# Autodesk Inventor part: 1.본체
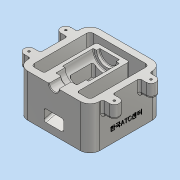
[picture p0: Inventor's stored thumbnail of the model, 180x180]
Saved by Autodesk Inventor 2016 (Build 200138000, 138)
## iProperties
Created: 2018-01
Part Number: 1.본체
Material: 알루미늄 6061
Document SubType Name: Modeling
Designer: Administrator
Density: 2.7 g/cm^3
Appearance: 알루미늄 - 평지
Mass: 995.363 g
Surface Area: 835.116 cm^2
Volume: 368.653 cm^3
Author: Administrator
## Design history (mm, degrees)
sketch "스케치1"
  geometry: L1 (-55, -55)-(55, -55); L2 (55, -55)-(55, 55); L3 (55, 55)-(-55, 55); L4 (-55, 55)-(-55, -55); L5 (-55, -55)-(55, 55); L6 (55, -55)-(-55, 55); 1 further point
  constraints: 12 end point, 2 midpoint, 2 parallel, 1 horizontal, 1 perpendicular
  dimensions: "d0" = 110 distance of L3.end L2.end; "d1" = 110 distance of L2.end L1.end
extrude "돌출1" new body sketch "스케치1" distance "d2" = 65; taper "d3" = 0 deg
sketch "스케치2"
  geometry: L1 (-55, -55)-(55, -55) reference; L2 (55, -55)-(55, 55) reference; L3 (55, 55)-(-55, 55) reference; L4 (-55, 55)-(-55, -55) reference; L5 (55, 35.5)-(65, 35.5); L6 (65, 35.5)-(65, 20.5); L7 (65, 20.5)-(55, 20.5); L8 (55, 20.5)-(55, 35.5); A1 r 7.5 centre (65, 28) between (65, 20.5) and (65, 35.5); 1 further point
  constraints: 8 end point, 2 parallel, 2 point on circle, 1 centre point, 1 horizontal, 1 midpoint, 1 perpendicular, 1 point on line
  dimensions: "d5" = 7.5 radius of A1; "d6" = 10 distance of L6.end L7.end; "d70" = 27 distance from line of A1.centre L3
extrude "돌출2" join sketch "스케치2" distance "d7" = 20; taper "d8" = 0 deg
sketch "스케치3"
  geometry: L1 (-45, 45)-(45, 45); L2 (45, 45)-(45, -45); L3 (45, -45)-(-45, -45); L4 (-45, -45)-(-45, 45); L5 (-45, 45)-(45, -45); L6 (45, 45)-(-45, -45); 1 further point
  constraints: 12 end point, 2 midpoint, 2 parallel, 1 horizontal, 1 perpendicular
  dimensions: "d9" = 90 distance of L2.end L3.end; "d10" = 90 distance of L1.end L2.end
extrude "돌출3" cut sketch "스케치3" stored distance "d11" = 20; taper "d12" = 0 deg
sketch "스케치4"
  geometry: L1 (-55, -55)-(55, -55) reference; L2 (55, 55)-(-55, 55) reference; L3 (-25, 35)-(25, 35); L4 (25, 35)-(25, -55); L5 (25, -55)-(-25, -55); L6 (-25, -55)-(-25, 35); 2 further points
  constraints: 8 end point, 2 parallel, 1 horizontal, 1 midpoint, 1 perpendicular, 1 point on line, 1 vertical alignment
  dimensions: "d13" = 50 distance between parallel lines of L4 L6; "d14" = 20 distance between parallel lines of L2 L3
extrude "돌출4" join sketch "스케치4" distance "d15" = 65; taper "d16" = 0 deg
sketch "스케치5"
  geometry: L1 (-55, 0)-(-55, 65) reference; L2 (-55, 65)-(-55, 57.5); L3 (-55, 57.5)-(-36, 57.5); L4 (-36, 57.5)-(-36, 49); L5 (-36, 49)-(-22, 49); L6 (-22, 49)-(-22, 45); L7 (-22, 45)-(25, 45); L8 (55, 65)-(35.5, 65) reference; L9 (-35.5, 65)-(-55, 65) reference; L10 (-55, 65)-(30, 65); L11 (-45, 65)-(45, 65) reference; L12 (25, 45)-(25, 50); L13 (25, 50)-(30, 50); L14 (30, 50)-(30, 65); 1 further point
  constraints: 20 end point, 6 perpendicular, 2 point on line, 1 collinear, 1 horizontal, 1 vertical
  dimensions: "d17" = 19 distance of L2.end L3.end; "d18" = 14 distance of L4.end L5.end; "d19" = 47 distance of L6.end L7.end; "d20" = 5 distance of L12.end L13.end; "d21" = 15 diameter of L3 L10; "d22" = 32 diameter of L5 L10; "d23" = 40 diameter of L7 L10; "d25" = 15 distance from line of L10.end L13
revolve "회전1" sketch "스케치5" stored, may be unused: angle "d26" = 90 deg
sketch "스케치6"
  geometry: L1 (35, 0)-(35, 30); L2 (35, 65)-(35, 0) reference; L3 (35, 30)-(-45, 8.564); L4 (-45, 8.564)-(-45, 0); L5 (45, 0)-(-45, 0) reference; L6 (-45, 0)-(35, 0); L7 (-22, 45)-(25, 45) reference; L8 (-17, 45)-(20, 45); L9 (-55, 0)-(-55, 65) reference; L10 (-55, 11.061)-(-55, 29.061); L11 (-55, 29.061)-(-17, 39.243); L12 (-17, 39.243)-(-17, 45); L13 (-45, 65)-(-45, 0) reference; L14 (-55, 11.061)-(20, 31.157); L15 (20, 31.157)-(20, 45); 3 further points
  constraints: 20 end point, 6 point on line, 4 parallel, 2 midpoint, 1 coincident, 1 collinear
  dimensions: "d27" = 30 distance of L1.start L1.end; "d28" = 105 deg angle of L4 L3; "d29" = 5 distance between parallel lines of L3 L14; "d30" = 37 distance of L8.start L8.end; "d31" = 75 deg angle of L9 L11; "d32" = 18 distance of L10.start L10.end; "d54" = 10 distance between parallel lines of L9 L4
extrude "돌출5" cut sketch "스케치6" stored distance "d33" = 30; taper "d34" = 0 deg
extrude "돌출6" cut sketch "스케치6" stored distance "d35" = 50; taper "d36" = 0 deg
node "작업 평면1"
sketch "스케치7"
  geometry: L1 (-15, -17)-(15, -17); L2 (15, -17)-(15, 20); L3 (15, 20)-(-15, 20); L4 (-15, 20)-(-15, -17); L5 (0, 20)-(0, -17) reference; L6 (-15, -17)-(15, 20); L7 (15, -17)-(-15, 20); 2 further points
  constraints: 12 end point, 3 midpoint, 2 parallel, 1 horizontal, 1 perpendicular
  dimensions: "d38" = 30 distance of L3.end L2.end; "d39" = 37 distance of L2.end L1.end
extrude "돌출7" cut sketch "스케치7" stored distance "d40" = 50; taper "d41" = 0 deg
fillet "모깎기1" dims "d42" = 1
fillet "모깎기2" dims "d43" = 3
fillet "모깎기3" dims "d44" = 15
fillet "모깎기4" dims "d45" = 3
fillet "모깎기5" dims "d46" = 3
fillet "모깎기6" dims "d48" = 5
chamfer "모따기1" distance "d50" = 1; stored, may be unused: second distance "d51" = 2, angle "d52" = 45 deg
fillet "모깎기7" dims "d53" = 3
hole "구멍1" diameter "d59" = 3.242; stored, may be unused: countersink angle "d63" = 90 deg, drill point angle "d65" = 118 deg; dims "d57" = 10, "d58" = 10, "d60" = 9, "d61" = 4, "d62" = 2, "d64" = 11
fillet "모깎기10" dims "d66" = 3
sketch "스케치8"
  geometry: L1 (0, 0)-(0, 80) reference; 3 further points
  constraints: 1 horizontal alignment, 1 midpoint, 1 other
  dimensions: "d67" = 20 distance of point (0, 40) point (-20, 40)
feature "엠보싱1" sketch "스케치8" dims "d0" = 110, "d1" = 110, "d68" = 0.5, "d69" = 0
node "솔리드1"
mirror "대칭1"
mirror "대칭2"
mirror "대칭3"
mirror "대칭4"
